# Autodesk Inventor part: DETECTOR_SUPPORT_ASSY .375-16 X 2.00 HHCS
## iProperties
Shininess: 64.0
Length Units: 11272
Angle Units: 11279
Time Units: 11290
Mass Units: 11286
Length Display Precision: 3
Angle Display Precision: 2
Compacted: True
Part Number: DETECTOR_SUPPORT_ASSY .375-16 X 2.00 HHCS
Document SubType Name: Modeling
Created: 2004-08
Designer: John Blackburn
Material: STAINLESS_STEEL, AUSTENITIC
Manufacturer: Standard
Standards Organization: Custom
Density: 0.0
Volumn: 0.0
Area: 0.0
PropertySet Name: Model Information
Control State: 0
Master: False
Checked Out: False
Author: John Blackburn
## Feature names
1. Base1
